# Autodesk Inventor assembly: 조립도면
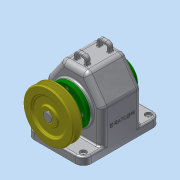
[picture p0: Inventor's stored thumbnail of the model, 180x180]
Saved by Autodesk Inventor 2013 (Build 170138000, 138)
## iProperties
Created: 2016-12
Part Number: 조립도면
Document SubType Name: Assembly
Designer: dgall
Author: dgall
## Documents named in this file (15)
- C:\Users\dgall\Desktop\461207V1012\조립도면.iam
- C:\Users\dgall\Desktop\461207V1012\본체.ipt
- C:\Users\dgall\Desktop\461207V1012\V-벨트풀리.ipt
- C:\Users\dgall\Desktop\461207V1012\뒤커버.ipt
- C:\Users\dgall\Desktop\461207V1012\멈춤나사 - M4x10.ipt
- C:\Users\dgall\Desktop\461207V1012\베어링 6203.ipt
- C:\Users\dgall\Desktop\461207V1012\볼트 M3 x 8.ipt
- C:\Users\dgall\Desktop\461207V1012\볼트 M3 x 10.ipt
- C:\Users\dgall\Desktop\461207V1012\부시.ipt
- C:\Users\dgall\Desktop\461207V1012\스퍼기어.ipt
- C:\Users\dgall\Desktop\461207V1012\앞커버.ipt
- C:\Users\dgall\Desktop\461207V1012\오일씰 28 40 8.ipt
- C:\Users\dgall\Desktop\461207V1012\축.ipt
- C:\Users\dgall\Desktop\461207V1012\키 - 5 x 5 x 18.ipt
- C:\Users\dgall\Desktop\461207V1012\키 - 6 x 6 x 22.ipt
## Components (9 placed, 3 different names)
1. V-벨트풀리:1
2. ISO 4762 M3 x 8:1
3. ISO 4762 M3 x 8:2
4. ISO 4762 M3 x 8:3
5. ISO 4762 M3 x 8:4
6. ISO 4762 M3 x 10:1
7. ISO 4762 M3 x 10:2
8. ISO 4762 M3 x 10:3
9. ISO 4762 M3 x 10:4
